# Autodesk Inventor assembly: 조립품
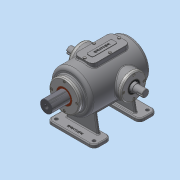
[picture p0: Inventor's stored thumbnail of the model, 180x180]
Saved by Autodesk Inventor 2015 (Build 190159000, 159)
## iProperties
Created: 2016-06
Part Number: 조립품
Document SubType Name: Assembly
Designer: nami
Author: nami
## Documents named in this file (15)
- C:\Users\nami\Desktop\Manufacturing1급\공용부품\조립품.iam
- C:\Users\nami\Desktop\Manufacturing1급\공용부품\베어링 6205.ipt
- 베어링 6205.ipt
- C:\Users\nami\Desktop\Manufacturing1급\공용부품\본체.ipt
- C:\Users\nami\Desktop\Manufacturing1급\공용부품\볼트 M4x0.7.ipt
- C:\Users\nami\Desktop\Manufacturing1급\공용부품\부시.ipt
- C:\Users\nami\Desktop\Manufacturing1급\공용부품\상부커버.ipt
- C:\Users\nami\Desktop\Manufacturing1급\공용부품\슬라이드 커버.ipt
- C:\Users\nami\Desktop\Manufacturing1급\공용부품\슬라이드.ipt
- C:\Users\nami\Desktop\Manufacturing1급\공용부품\오일실.ipt
- 오일실.ipt
- C:\Users\nami\Desktop\Manufacturing1급\공용부품\육각머리볼트 M4.ipt
- C:\Users\nami\Desktop\Manufacturing1급\공용부품\축 커버.ipt
- C:\Users\nami\Desktop\Manufacturing1급\공용부품\편심축.ipt
- C:\Users\nami\Desktop\Manufacturing1급\공용부품\가변스프링.ipt
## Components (13 placed, 2 different names)
1. 가변스프링:1
2. M4x0.7:2
3. M4x0.7:3
4. M4x0.7:4
5. M4x0.7:5
6. M4x0.7:1
7. M4x0.7:6
8. M4x0.7:7
9. M4x0.7:8
10. M4x0.7:9
11. M4x0.7:10
12. M4x0.7:11
13. M4x0.7:12
